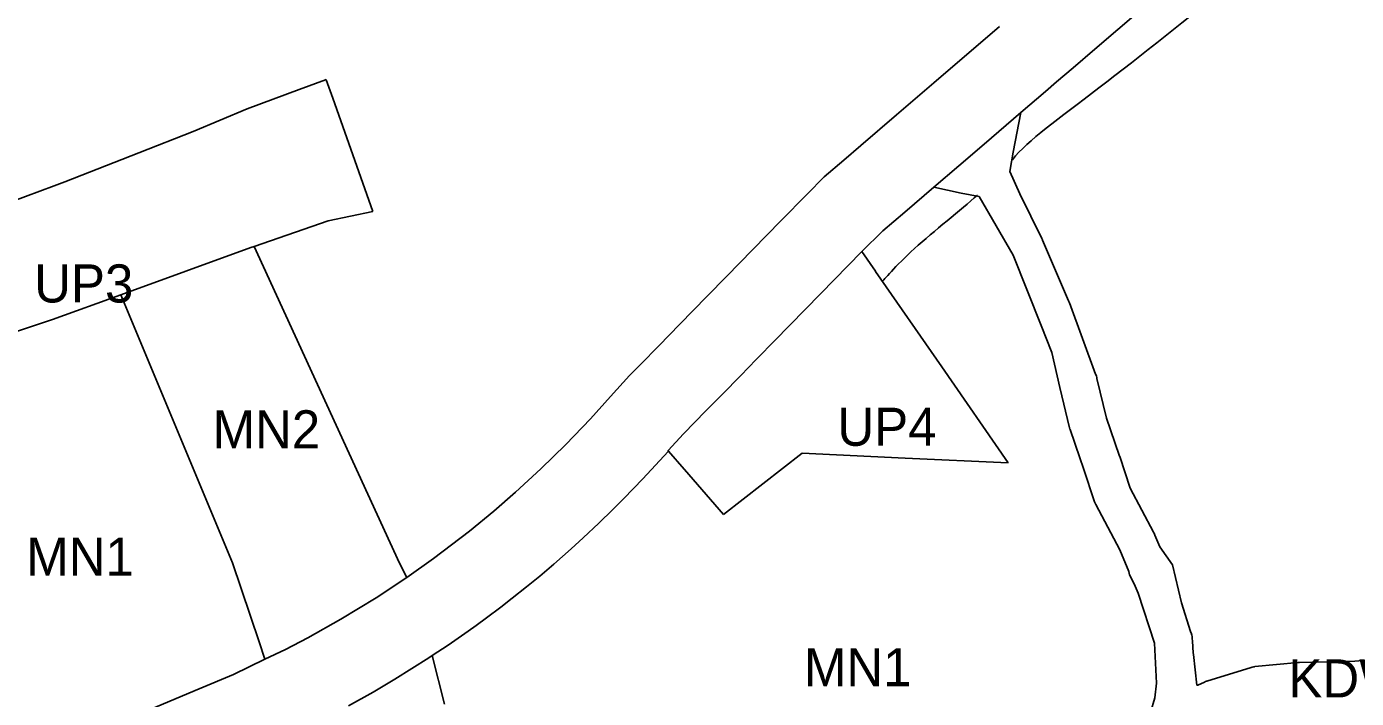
# Model space of a CAD drawing. Extents: x 7413438 to 7416393, y 5541665 to 5544118.
# Drawn here: x 7414642.6 to 7414851.9, y 5542863.7 to 5542969.5 of the extents above; entities that cross this region are included whole.
import ezdxf

# ---------------------------------------------------------------- set-up
doc = ezdxf.new("R2010")
doc.units = 0
for name, color, linetype in [('linie_rozgraniczajace', 7, 'Continuous'), ('linie_zabudowy_nieprzekraczalne', 7, 'Continuous'), ('oznaczenia_przeznaczen', 7, 'Continuous')]:
    doc.layers.add(name, color=color, linetype=linetype)

msp = doc.modelspace()

# ---------------------------------------------------------------- linework, layer by layer
at = {"layer": 'linie_rozgraniczajace'}
for p, q in [((7414814.37, 5542969.1), (7414817.63, 5542971.89)), ((7414795.77, 5542969.55), (7414785.4, 5542960.67)), ((7414810.76, 5542966), (7414814.37, 5542969.1)), ((7414807.32, 5542963.05), (7414810.76, 5542966)), ((7414804.74, 5542960.84), (7414807.32, 5542963.05)), ((7414677.33, 5542956.61), (7414685.5, 5542959.63)), ((7414685.5, 5542959.63), (7414689.65, 5542961.16)), ((7414689.65, 5542961.16), (7414689.75, 5542961.2)), ((7414689.75, 5542961.2), (7414689.76, 5542961.17)), ((7414689.76, 5542961.17), (7414690.79, 5542958.27)), ((7414785.4, 5542960.67), (7414779.55, 5542955.66)), ((7414802.98, 5542959.33), (7414804.74, 5542960.84)), ((7414690.79, 5542958.27), (7414697.12, 5542940.45)), ((7414799.1, 5542956), (7414802.98, 5542959.33)), ((7414668.84, 5542953.03), (7414677.33, 5542956.61)), ((7414779.55, 5542955.66), (7414773.92, 5542950.84)), ((7414793.33, 5542951.05), (7414799.1, 5542956)), ((7414797.92, 5542949.76), (7414799.1, 5542956)), ((7414660.27, 5542949.68), (7414668.84, 5542953.03)), ((7414648.62, 5542945.11), (7414660.27, 5542949.68)), ((7414773.92, 5542950.84), (7414771.22, 5542948.52)), ((7414789.33, 5542947.62), (7414793.33, 5542951.05)), ((7414797.37, 5542946.74), (7414797.92, 5542949.76)), ((7414771.22, 5542948.52), (7414768.17, 5542945.91)), ((7414785.4, 5542944.24), (7414789.33, 5542947.62)), ((7414646.95, 5542944.48), (7414648.62, 5542945.11)), ((7414768.17, 5542945.91), (7414765.49, 5542943.17)), ((7414798.96, 5542943.22), (7414797.37, 5542946.74)), ((7414634.81, 5542939.96), (7414646.95, 5542944.48)), ((7414765.49, 5542943.17), (7414761.35, 5542938.94)), ((7414780.85, 5542940.34), (7414785.4, 5542944.24)), ((7414785.4, 5542944.24), (7414789.7, 5542943.31)), ((7414789.7, 5542943.31), (7414792.52, 5542942.8)), ((7414802.39, 5542936.2), (7414798.96, 5542943.22)), ((7414792.52, 5542942.8), (7414797.88, 5542933.55)), ((7414690.1, 5542938.95), (7414678.42, 5542934.93)), ((7414697.12, 5542940.45), (7414690.1, 5542938.95)), ((7414761.35, 5542938.94), (7414756.93, 5542934.43)), ((7414777.39, 5542937.37), (7414780.85, 5542940.34)), ((7414774.06, 5542934.11), (7414777.39, 5542937.37)), ((7414677.9, 5542934.74), (7414657.46, 5542927.28)), ((7414678.42, 5542934.93), (7414677.9, 5542934.74)), ((7414678.42, 5542934.93), (7414701.3, 5542885.05)), ((7414802.42, 5542936.13), (7414802.39, 5542936.2)), ((7414802.45, 5542936.07), (7414802.42, 5542936.13)), ((7414802.49, 5542935.99), (7414802.45, 5542936.07)), ((7414802.52, 5542935.93), (7414802.49, 5542935.99)), ((7414806.62, 5542926.34), (7414802.52, 5542935.93)), ((7414756.93, 5542934.43), (7414752.76, 5542930.17)), ((7414767.56, 5542927.44), (7414774.06, 5542934.12)), ((7414774.06, 5542934.12), (7414774.06, 5542934.11)), ((7414774.06, 5542934.11), (7414776.21, 5542931.02)), ((7414797.88, 5542933.55), (7414802.33, 5542922.45)), ((7414776.21, 5542931.02), (7414776.23, 5542930.98)), ((7414776.23, 5542930.98), (7414786.65, 5542915.96)), ((7414752.76, 5542930.17), (7414749.74, 5542927.08)), ((7414657.46, 5542927.28), (7414646.68, 5542923.4)), ((7414675.02, 5542885.08), (7414657.46, 5542927.28)), ((7414749.74, 5542927.08), (7414745.38, 5542922.63)), ((7414760.34, 5542920.06), (7414767.56, 5542927.44)), ((7414806.65, 5542926.27), (7414806.62, 5542926.34)), ((7414806.69, 5542926.17), (7414806.65, 5542926.27)), ((7414806.71, 5542926.12), (7414806.69, 5542926.17)), ((7414806.73, 5542926.07), (7414806.71, 5542926.12)), ((7414806.74, 5542926.05), (7414806.73, 5542926.07)), ((7414810.88, 5542914.8), (7414806.74, 5542926.05)), ((7414646.68, 5542923.4), (7414640.38, 5542921.31)), ((7414745.38, 5542922.63), (7414742.17, 5542919.35)), ((7414802.33, 5542922.45), (7414803.99, 5542918.2)), ((7414757.66, 5542917.33), (7414760.34, 5542920.06)), ((7414742.17, 5542919.35), (7414739.17, 5542916.29)), ((7414803.99, 5542918.2), (7414805.25, 5542912.72)), ((7414739.17, 5542916.29), (7414737.52, 5542914.6)), ((7414754.64, 5542914.24), (7414756.58, 5542916.22)), ((7414756.58, 5542916.22), (7414757.1, 5542916.75)), ((7414757.1, 5542916.75), (7414757.66, 5542917.33)), ((7414786.65, 5542915.96), (7414797.13, 5542900.84)), ((7414737.52, 5542914.6), (7414734.52, 5542911.3)), ((7414752.44, 5542912), (7414754.64, 5542914.24)), ((7414810.95, 5542914.63), (7414810.88, 5542914.8)), ((7414810.99, 5542914.49), (7414810.95, 5542914.63)), ((7414811.05, 5542914.3), (7414810.99, 5542914.49)), ((7414811.05, 5542914.29), (7414811.05, 5542914.3)), ((7414811.09, 5542914.13), (7414811.05, 5542914.29)), ((7414812.57, 5542907.9), (7414811.09, 5542914.13)), ((7414811.09, 5542914.13), (7414811.09, 5542914.13)), ((7414749.53, 5542909.03), (7414752.44, 5542912)), ((7414805.25, 5542912.72), (7414806.77, 5542906.36)), ((7414734.52, 5542911.3), (7414731.36, 5542907.79)), ((7414731.36, 5542907.79), (7414727.49, 5542903.74)), ((7414745.99, 5542905.41), (7414749.53, 5542909.03)), ((7414813.9, 5542904.07), (7414812.57, 5542907.9)), ((7414743.57, 5542902.77), (7414745.99, 5542905.41)), ((7414806.77, 5542906.36), (7414806.78, 5542906.36)), ((7414806.78, 5542906.36), (7414806.83, 5542906.17)), ((7414806.83, 5542906.17), (7414806.86, 5542906.08)), ((7414806.86, 5542906.08), (7414808.4, 5542901.62)), ((7414727.49, 5542903.74), (7414723.56, 5542899.88)), ((7414814.65, 5542901.9), (7414813.9, 5542904.07)), ((7414739.62, 5542898.34), (7414743.58, 5542902.65)), ((7414743.58, 5542902.65), (7414743.57, 5542902.77)), ((7414743.63, 5542902.71), (7414743.58, 5542902.65)), ((7414746.09, 5542899.87), (7414743.63, 5542902.71)), ((7414764.7, 5542902.35), (7414752.28, 5542892.73)), ((7414780.9, 5542901.59), (7414764.7, 5542902.35)), ((7414797.13, 5542900.84), (7414780.9, 5542901.59)), ((7414808.4, 5542901.62), (7414808.99, 5542899.94)), ((7414814.66, 5542901.89), (7414814.65, 5542901.9)), ((7414814.67, 5542901.85), (7414814.66, 5542901.89)), ((7414814.68, 5542901.84), (7414814.67, 5542901.85)), ((7414816.34, 5542896.86), (7414814.68, 5542901.84)), ((7414723.56, 5542899.88), (7414719.58, 5542896.22)), ((7414746.16, 5542899.79), (7414746.09, 5542899.87)), ((7414752.28, 5542892.73), (7414746.16, 5542899.79)), ((7414808.99, 5542899.94), (7414810.72, 5542894.72)), ((7414736.64, 5542895.24), (7414739.62, 5542898.34)), ((7414819.99, 5542889.94), (7414816.34, 5542896.86)), ((7414719.58, 5542896.22), (7414716.14, 5542893.24)), ((7414734.91, 5542893.51), (7414736.64, 5542895.24)), ((7414810.72, 5542894.72), (7414810.77, 5542894.59)), ((7414716.14, 5542893.24), (7414712.31, 5542890.09)), ((7414732.7, 5542891.35), (7414734.91, 5542893.51)), ((7414810.77, 5542894.59), (7414810.85, 5542894.41)), ((7414810.85, 5542894.41), (7414810.92, 5542894.27)), ((7414810.92, 5542894.27), (7414814.69, 5542887.14)), ((7414730.21, 5542889.02), (7414732.7, 5542891.35)), ((7414712.31, 5542890.09), (7414706.65, 5542885.77)), ((7414728.32, 5542887.3), (7414730.21, 5542889.02)), ((7414820.05, 5542889.83), (7414819.99, 5542889.94)), ((7414820.12, 5542889.69), (7414820.05, 5542889.83)), ((7414820.16, 5542889.6), (7414820.12, 5542889.69)), ((7414820.21, 5542889.48), (7414820.16, 5542889.6)), ((7414821, 5542887.63), (7414820.21, 5542889.48)), ((7414725.58, 5542884.89), (7414728.32, 5542887.3)), ((7414814.69, 5542887.14), (7414816.12, 5542883.76)), ((7414822.98, 5542884.77), (7414821, 5542887.63)), ((7414679.2, 5542872.68), (7414675.02, 5542885.08)), ((7414701.3, 5542885.05), (7414702.44, 5542882.79)), ((7414706.65, 5542885.77), (7414702.44, 5542882.79)), ((7414723.38, 5542883.02), (7414725.58, 5542884.89)), ((7414824.37, 5542878.8), (7414822.98, 5542884.77)), ((7414702.44, 5542882.79), (7414697.62, 5542879.6)), ((7414721.31, 5542881.32), (7414723.38, 5542883.02)), ((7414816.12, 5542883.76), (7414816.21, 5542883.19)), ((7414816.21, 5542883.19), (7414816.95, 5542881.8)), ((7414719.03, 5542879.51), (7414721.31, 5542881.32)), ((7414816.95, 5542881.8), (7414817.58, 5542880.32)), ((7414817.58, 5542880.32), (7414820.12, 5542872.44)), ((7414697.62, 5542879.6), (7414692.07, 5542876.21)), ((7414714.98, 5542876.42), (7414717.27, 5542878.14)), ((7414717.27, 5542878.14), (7414719.03, 5542879.51)), ((7414825.83, 5542874.28), (7414824.37, 5542878.8)), ((7414692.07, 5542876.21), (7414686.89, 5542873.3)), ((7414713.38, 5542875.25), (7414714.98, 5542876.42)), ((7414708.96, 5542872.15), (7414712.11, 5542874.34)), ((7414712.11, 5542874.34), (7414713.38, 5542875.25)), ((7414825.83, 5542874.26), (7414825.83, 5542874.28)), ((7414825.95, 5542873.91), (7414825.83, 5542874.26)), ((7414825.95, 5542873.89), (7414825.95, 5542873.91)), ((7414826.01, 5542873.7), (7414825.95, 5542873.89)), ((7414680.12, 5542869.92), (7414679.2, 5542872.68)), ((7414686.89, 5542873.3), (7414683.35, 5542871.44)), ((7414706.47, 5542870.48), (7414708.96, 5542872.15)), ((7414820.12, 5542872.44), (7414820.48, 5542866.15)), ((7414826.05, 5542873.5), (7414826.01, 5542873.7)), ((7414826.07, 5542873.31), (7414826.05, 5542873.5)), ((7414826.09, 5542873.16), (7414826.07, 5542873.31)), ((7414826.11, 5542872.78), (7414826.09, 5542873.16)), ((7414826.21, 5542870.93), (7414826.11, 5542872.78)), ((7414680.12, 5542869.92), (7414675.15, 5542867.53)), ((7414683.35, 5542871.44), (7414680.12, 5542869.92)), ((7414705.93, 5542870.13), (7414700.57, 5542866.76)), ((7414706.47, 5542870.48), (7414705.93, 5542870.13)), ((7414708.4, 5542862.85), (7414706.47, 5542870.48)), ((7414826.28, 5542870.64), (7414826.21, 5542870.93)), ((7414826.82, 5542865.84), (7414826.28, 5542870.64)), ((7414851.7, 5542869.63), (7414842.95, 5542869.39)), ((7414862.94, 5542870.55), (7414851.7, 5542869.63)), ((7414675.15, 5542867.53), (7414669.79, 5542865.24)), ((7414835.34, 5542868.63), (7414828.36, 5542866.46)), ((7414835.52, 5542868.68), (7414835.34, 5542868.63)), ((7414835.71, 5542868.72), (7414835.52, 5542868.68)), ((7414835.91, 5542868.74), (7414835.71, 5542868.72)), ((7414835.95, 5542868.75), (7414835.91, 5542868.74)), ((7414842.76, 5542869.38), (7414835.95, 5542868.75)), ((7414842.91, 5542869.39), (7414842.76, 5542869.38)), ((7414842.95, 5542869.39), (7414842.91, 5542869.39)), ((7414700.57, 5542866.76), (7414697.17, 5542864.75)), ((7414820.48, 5542866.15), (7414820.21, 5542863.86)), ((7414826.98, 5542865.85), (7414826.82, 5542865.84)), ((7414827.99, 5542866.32), (7414826.98, 5542865.85)), ((7414828.17, 5542866.39), (7414827.99, 5542866.32)), ((7414828.35, 5542866.46), (7414828.17, 5542866.39)), ((7414828.36, 5542866.46), (7414828.35, 5542866.46)), ((7414669.79, 5542865.24), (7414662.17, 5542862.07)), ((7414697.17, 5542864.75), (7414693.28, 5542862.58)), ((7414820.21, 5542863.86), (7414819.49, 5542861.51))]:
    msp.add_line(p, q, dxfattribs=at)
at = {"layer": 'linie_zabudowy_nieprzekraczalne'}
for points in [[(7414865.41, 5543001.51), (7414863.31, 5542999.93), (7414863.3, 5542999.93), (7414841.57, 5542983.67), (7414834.34, 5542978.05), (7414809.62, 5542958.24), (7414800.27, 5542951.67), (7414797.78, 5542948.59)], [(7414792.26, 5542943.02), (7414789.68, 5542940.65), (7414781.16, 5542934.1), (7414777.44, 5542929.51), (7414777.28, 5542929.4)]]:
    msp.add_open_spline(points, degree=3, dxfattribs=at)

# ---------------------------------------------------------------- texts
at = {"layer": 'oznaczenia_przeznaczen'}
for s, p in [('UP3', (7414643.8, 5542926.1)), ('UP4', (7414770.23, 5542903.53)), ('MN2', (7414671.88, 5542903.12)), ('MN1', (7414642.55, 5542883.08)), ('MN1', (7414764.96, 5542865.66)), ('KDW', (7414841.22, 5542863.9))]:
    msp.add_text(s, height=6, dxfattribs=at).set_placement(p)

doc.saveas('drawing.dxf')
